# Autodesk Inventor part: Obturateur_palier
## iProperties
Shininess: 64.0
Length Units: 11269
Angle Units: 11279
Time Units: 11290
Mass Units: 11283
Length Display Precision: 3
Angle Display Precision: 2
Compacted: True
Part Number: Obturateur_palier
Document SubType Name: Modeling
Created: 2008-02
Material: Acier inoxydable - 440C
Designer: Pascal
Density: 0.0
Volumn: 0.0
Area: 0.0
PropertySet Name: Model Information
Control State: 0
Master: False
Checked Out: False
DESIGNATION: pièce
Author: Pascal
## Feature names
1. Extrusion1
2. Extrusion2
